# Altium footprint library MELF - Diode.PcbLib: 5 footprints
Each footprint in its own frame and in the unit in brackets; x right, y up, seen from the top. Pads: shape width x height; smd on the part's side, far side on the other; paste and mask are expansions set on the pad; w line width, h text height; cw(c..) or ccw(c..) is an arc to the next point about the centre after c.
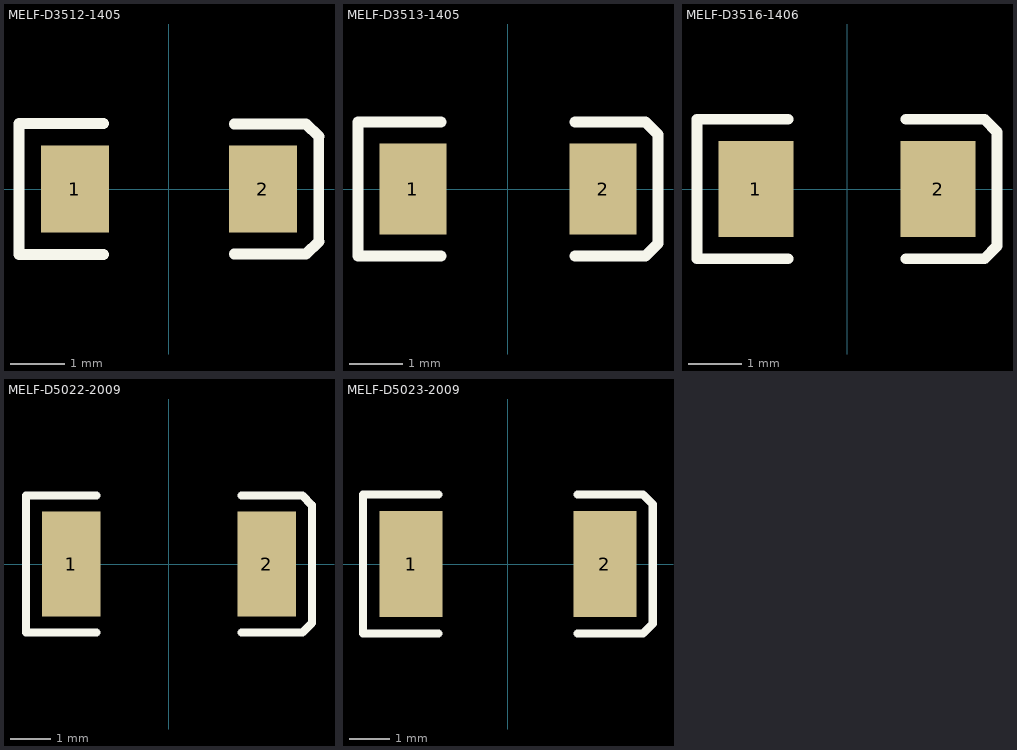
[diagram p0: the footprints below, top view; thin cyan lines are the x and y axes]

## MELF-D3512-1405 [mm]
pads (2):
  rect 1.25x1.6 smd: 1(-1.725,0) 2(1.725,0)
Top Overlay:
  lines w0.2: -1.2,-1.2 -2.75,-1.2 -2.75,1.2 -1.2,1.2 ; 1.2,-1.19 2.516,-1.19 2.755,-0.966 ; 1.2,1.19 2.516,1.19 2.755,0.966 ; 2.75,-0.966 2.75,0.966

## MELF-D3513-1405 [mm]
pads (2):
  rect 1.25x1.7 smd: 1(-1.775,0) 2(1.775,0)
Top Overlay:
  lines w0.2: -2.8,-1.25 -1.25,-1.25 ; -2.8,-1.2 -2.8,1.2 ; -2.8,1.25 -1.25,1.25 ; 1.25,-1.25 2.566,-1.25 2.8,-1.016 2.8,1.016 2.566,1.25 1.25,1.25

## MELF-D3516-1406 [mm]
pads (2):
  rect 1.4x1.8 smd: 1(-1.7,0) 2(1.7,0)
Top Overlay:
  lines w0.2: -1.1,-1.3 -2.8,-1.3 -2.8,1.3 -1.1,1.3 ; 1.1,-1.3 2.566,-1.3 2.8,-1.066 2.8,1.066 2.566,1.3 1.1,1.3

## MELF-D5022-2009 [mm]
pads (2):
  rect 1.45x2.6 smd: 1(-2.425,0) 2(2.425,0)
Top Overlay:
  lines w0.2: -1.8,-1.7 -3.55,-1.7 -3.55,1.7 -1.8,1.7 ; 1.8,-1.7 3.316,-1.7 3.55,-1.466 3.55,1.466 ; 1.8,1.7 3.316,1.7 3.54,1.466

## MELF-D5023-2009 [mm]
pads (2):
  rect 1.55x2.6 smd: 1(-2.375,0) 2(2.375,0)
Top Overlay:
  lines w0.2: -1.7,-1.7 -3.55,-1.7 -3.55,1.7 -1.7,1.7 ; 1.7,-1.7 3.311,-1.7 3.545,-1.466 3.545,1.466 3.311,1.7 1.7,1.7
